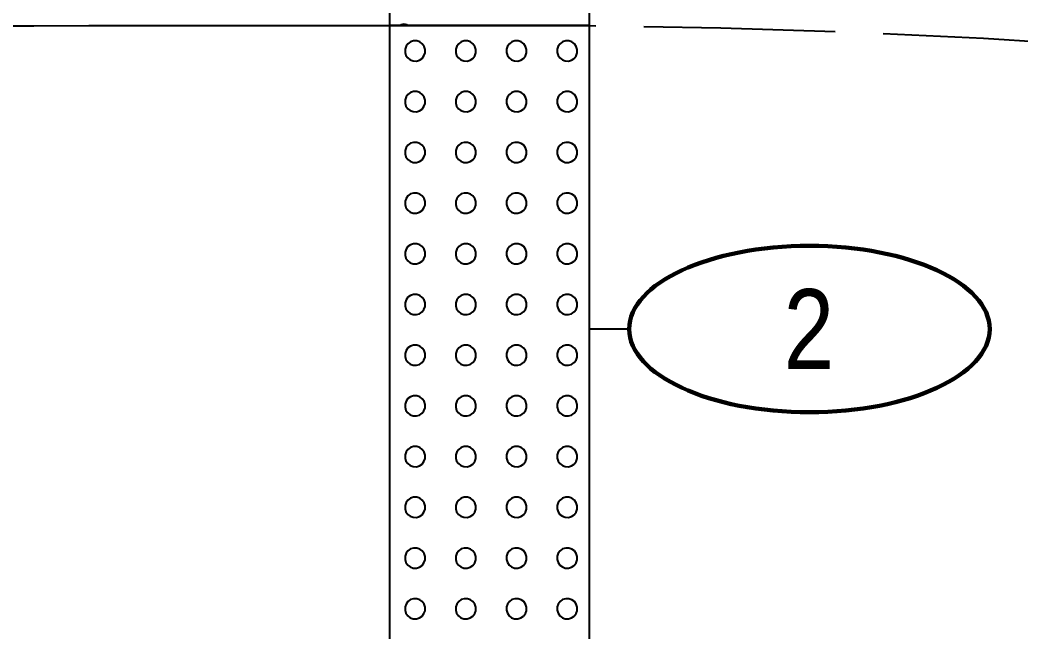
# Model space of a CAD drawing. Extents: x -582 to 653, y -817 to -3.
# Drawn here: x -30.1 to -17.56, y -223.19 to -215.52 of the extents above; entities that cross this region are included whole.
import ezdxf
from ezdxf.enums import TextEntityAlignment as Align

# ---------------------------------------------------------------- set-up
doc = ezdxf.new("R2010")
doc.units = 0
doc.header["$LTSCALE"] = 0.4
doc.linetypes.add('LONG_DASHED', pattern=[7.5, 6, -1.5])
doc.layers.add('26', color=7, linetype='LONG_DASHED', lineweight=40)
doc.layers.add('27', color=7, linetype='Continuous', lineweight=40)

msp = doc.modelspace()

# ---------------------------------------------------------------- linework, layer by layer
at = {"layer": '26'}
msp.add_spline([(-40.288, -215.7398), (-29.2387, -215.5929), (-25.4713, -215.5929), (-22.9713, -215.5929), (3.2787, -218.2344)], degree=3, dxfattribs=at)
at = {"layer": '27'}
for p, q in [((-29.2387, -215.5929), (-25.4713, -215.5929)), ((-22.4714, -219.3929), (-22.9714, -219.3929))]:
    msp.add_line(p, q, dxfattribs=at)
for points in [[(-25.4713, -200.5929), (-22.9713, -200.5929), (-22.9713, -215.5929), (-25.4713, -215.5929)], [(-25.4713, -215.5929), (-22.9713, -215.5929), (-22.9713, -226.0929), (-25.4713, -226.0929)], [(-25.2551, -215.5834), (-25.2932, -215.5732), (-25.3313, -215.5834), (-25.3408, -215.5929), (-25.2455, -215.5929)], [(-25.0267, -215.9104), (-25.0283, -215.8907), (-25.0404, -215.853), (-25.0636, -215.8209), (-25.0954, -215.7975), (-25.133, -215.785), (-25.1725, -215.7847), (-25.2103, -215.7965), (-25.2426, -215.8194), (-25.2662, -215.851), (-25.2791, -215.8885), (-25.2798, -215.928), (-25.2683, -215.9659), (-25.2457, -215.9983), (-25.2142, -216.0223), (-25.1769, -216.0354), (-25.1374, -216.0365), (-25.0994, -216.0253), (-25.0667, -216.003), (-25.0425, -215.9718), (-25.029, -215.9346)], [(-24.3917, -215.9104), (-24.3933, -215.8907), (-24.4054, -215.853), (-24.4286, -215.8209), (-24.4604, -215.7975), (-24.498, -215.785), (-24.5375, -215.7847), (-24.5753, -215.7965), (-24.6076, -215.8194), (-24.6312, -215.851), (-24.6441, -215.8885), (-24.6448, -215.928), (-24.6333, -215.9659), (-24.6107, -215.9983), (-24.5792, -216.0223), (-24.5419, -216.0354), (-24.5024, -216.0365), (-24.4644, -216.0253), (-24.4317, -216.003), (-24.4075, -215.9718), (-24.394, -215.9346)], [(-23.7567, -215.9104), (-23.7583, -215.8907), (-23.7704, -215.853), (-23.7936, -215.8209), (-23.8254, -215.7975), (-23.863, -215.785), (-23.9025, -215.7847), (-23.9403, -215.7965), (-23.9726, -215.8194), (-23.9962, -215.851), (-24.0091, -215.8885), (-24.0098, -215.928), (-23.9983, -215.9659), (-23.9757, -215.9983), (-23.9442, -216.0223), (-23.9069, -216.0354), (-23.8674, -216.0365), (-23.8294, -216.0253), (-23.7967, -216.003), (-23.7725, -215.9718), (-23.759, -215.9346)], [(-23.1217, -215.9104), (-23.1233, -215.8907), (-23.1354, -215.853), (-23.1586, -215.8209), (-23.1904, -215.7975), (-23.228, -215.785), (-23.2675, -215.7847), (-23.3053, -215.7965), (-23.3376, -215.8194), (-23.3612, -215.851), (-23.3741, -215.8885), (-23.3748, -215.928), (-23.3633, -215.9659), (-23.3407, -215.9983), (-23.3092, -216.0223), (-23.2719, -216.0354), (-23.2324, -216.0365), (-23.1944, -216.0253), (-23.1617, -216.003), (-23.1375, -215.9718), (-23.124, -215.9346)], [(-25.0267, -216.5454), (-25.0283, -216.5257), (-25.0404, -216.488), (-25.0636, -216.4559), (-25.0954, -216.4325), (-25.133, -216.42), (-25.1725, -216.4197), (-25.2103, -216.4315), (-25.2426, -216.4544), (-25.2662, -216.486), (-25.2791, -216.5235), (-25.2798, -216.563), (-25.2683, -216.6009), (-25.2457, -216.6333), (-25.2142, -216.6573), (-25.1769, -216.6704), (-25.1374, -216.6715), (-25.0994, -216.6603), (-25.0667, -216.638), (-25.0425, -216.6068), (-25.029, -216.5696)], [(-24.3917, -216.5454), (-24.3933, -216.5257), (-24.4054, -216.488), (-24.4286, -216.4559), (-24.4604, -216.4325), (-24.498, -216.42), (-24.5375, -216.4197), (-24.5753, -216.4315), (-24.6076, -216.4544), (-24.6312, -216.486), (-24.6441, -216.5235), (-24.6448, -216.563), (-24.6333, -216.6009), (-24.6107, -216.6333), (-24.5792, -216.6573), (-24.5419, -216.6704), (-24.5024, -216.6715), (-24.4644, -216.6603), (-24.4317, -216.638), (-24.4075, -216.6068), (-24.394, -216.5696)], [(-23.7567, -216.5454), (-23.7583, -216.5257), (-23.7704, -216.488), (-23.7936, -216.4559), (-23.8254, -216.4325), (-23.863, -216.42), (-23.9025, -216.4197), (-23.9403, -216.4315), (-23.9726, -216.4544), (-23.9962, -216.486), (-24.0091, -216.5235), (-24.0098, -216.563), (-23.9983, -216.6009), (-23.9757, -216.6333), (-23.9442, -216.6573), (-23.9069, -216.6704), (-23.8674, -216.6715), (-23.8294, -216.6603), (-23.7967, -216.638), (-23.7725, -216.6068), (-23.759, -216.5696)], [(-23.1217, -216.5454), (-23.1233, -216.5257), (-23.1354, -216.488), (-23.1586, -216.4559), (-23.1904, -216.4325), (-23.228, -216.42), (-23.2675, -216.4197), (-23.3053, -216.4315), (-23.3376, -216.4544), (-23.3612, -216.486), (-23.3741, -216.5235), (-23.3748, -216.563), (-23.3633, -216.6009), (-23.3407, -216.6333), (-23.3092, -216.6573), (-23.2719, -216.6704), (-23.2324, -216.6715), (-23.1944, -216.6603), (-23.1617, -216.638), (-23.1375, -216.6068), (-23.124, -216.5696)], [(-25.0267, -217.1804), (-25.0283, -217.1607), (-25.0404, -217.123), (-25.0636, -217.0909), (-25.0954, -217.0675), (-25.133, -217.055), (-25.1725, -217.0547), (-25.2103, -217.0665), (-25.2426, -217.0894), (-25.2662, -217.121), (-25.2791, -217.1585), (-25.2798, -217.198), (-25.2683, -217.2359), (-25.2457, -217.2683), (-25.2142, -217.2923), (-25.1769, -217.3054), (-25.1374, -217.3065), (-25.0994, -217.2953), (-25.0667, -217.273), (-25.0425, -217.2418), (-25.029, -217.2046)], [(-24.3917, -217.1804), (-24.3933, -217.1607), (-24.4054, -217.123), (-24.4286, -217.0909), (-24.4604, -217.0675), (-24.498, -217.055), (-24.5375, -217.0547), (-24.5753, -217.0665), (-24.6076, -217.0894), (-24.6312, -217.121), (-24.6441, -217.1585), (-24.6448, -217.198), (-24.6333, -217.2359), (-24.6107, -217.2683), (-24.5792, -217.2923), (-24.5419, -217.3054), (-24.5024, -217.3065), (-24.4644, -217.2953), (-24.4317, -217.273), (-24.4075, -217.2418), (-24.394, -217.2046)], [(-23.7567, -217.1804), (-23.7583, -217.1607), (-23.7704, -217.123), (-23.7936, -217.0909), (-23.8254, -217.0675), (-23.863, -217.055), (-23.9025, -217.0547), (-23.9403, -217.0665), (-23.9726, -217.0894), (-23.9962, -217.121), (-24.0091, -217.1585), (-24.0098, -217.198), (-23.9983, -217.2359), (-23.9757, -217.2683), (-23.9442, -217.2923), (-23.9069, -217.3054), (-23.8674, -217.3065), (-23.8294, -217.2953), (-23.7967, -217.273), (-23.7725, -217.2418), (-23.759, -217.2046)], [(-23.1217, -217.1804), (-23.1233, -217.1607), (-23.1354, -217.123), (-23.1586, -217.0909), (-23.1904, -217.0675), (-23.228, -217.055), (-23.2675, -217.0547), (-23.3053, -217.0665), (-23.3376, -217.0894), (-23.3612, -217.121), (-23.3741, -217.1585), (-23.3748, -217.198), (-23.3633, -217.2359), (-23.3407, -217.2683), (-23.3092, -217.2923), (-23.2719, -217.3054), (-23.2324, -217.3065), (-23.1944, -217.2953), (-23.1617, -217.273), (-23.1375, -217.2418), (-23.124, -217.2046)], [(-25.0267, -217.8154), (-25.0283, -217.7957), (-25.0404, -217.758), (-25.0636, -217.7259), (-25.0954, -217.7025), (-25.133, -217.69), (-25.1725, -217.6897), (-25.2103, -217.7015), (-25.2426, -217.7244), (-25.2662, -217.756), (-25.2791, -217.7935), (-25.2798, -217.833), (-25.2683, -217.8709), (-25.2457, -217.9033), (-25.2142, -217.9273), (-25.1769, -217.9404), (-25.1374, -217.9415), (-25.0994, -217.9303), (-25.0667, -217.908), (-25.0425, -217.8768), (-25.029, -217.8396)], [(-24.3917, -217.8154), (-24.3933, -217.7957), (-24.4054, -217.758), (-24.4286, -217.7259), (-24.4604, -217.7025), (-24.498, -217.69), (-24.5375, -217.6897), (-24.5753, -217.7015), (-24.6076, -217.7244), (-24.6312, -217.756), (-24.6441, -217.7935), (-24.6448, -217.833), (-24.6333, -217.8709), (-24.6107, -217.9033), (-24.5792, -217.9273), (-24.5419, -217.9404), (-24.5024, -217.9415), (-24.4644, -217.9303), (-24.4317, -217.908), (-24.4075, -217.8768), (-24.394, -217.8396)], [(-23.7567, -217.8154), (-23.7583, -217.7957), (-23.7704, -217.758), (-23.7936, -217.7259), (-23.8254, -217.7025), (-23.863, -217.69), (-23.9025, -217.6897), (-23.9403, -217.7015), (-23.9726, -217.7244), (-23.9962, -217.756), (-24.0091, -217.7935), (-24.0098, -217.833), (-23.9983, -217.8709), (-23.9757, -217.9033), (-23.9442, -217.9273), (-23.9069, -217.9404), (-23.8674, -217.9415), (-23.8294, -217.9303), (-23.7967, -217.908), (-23.7725, -217.8768), (-23.759, -217.8396)], [(-23.1217, -217.8154), (-23.1233, -217.7957), (-23.1354, -217.758), (-23.1586, -217.7259), (-23.1904, -217.7025), (-23.228, -217.69), (-23.2675, -217.6897), (-23.3053, -217.7015), (-23.3376, -217.7244), (-23.3612, -217.756), (-23.3741, -217.7935), (-23.3748, -217.833), (-23.3633, -217.8709), (-23.3407, -217.9033), (-23.3092, -217.9273), (-23.2719, -217.9404), (-23.2324, -217.9415), (-23.1944, -217.9303), (-23.1617, -217.908), (-23.1375, -217.8768), (-23.124, -217.8396)], [(-25.0267, -218.4504), (-25.0283, -218.4307), (-25.0404, -218.393), (-25.0636, -218.3609), (-25.0954, -218.3375), (-25.133, -218.325), (-25.1725, -218.3247), (-25.2103, -218.3365), (-25.2426, -218.3594), (-25.2662, -218.391), (-25.2791, -218.4285), (-25.2798, -218.468), (-25.2683, -218.5059), (-25.2457, -218.5383), (-25.2142, -218.5623), (-25.1769, -218.5754), (-25.1374, -218.5765), (-25.0994, -218.5653), (-25.0667, -218.543), (-25.0425, -218.5118), (-25.029, -218.4746)], [(-24.3917, -218.4504), (-24.3933, -218.4307), (-24.4054, -218.393), (-24.4286, -218.3609), (-24.4604, -218.3375), (-24.498, -218.325), (-24.5375, -218.3247), (-24.5753, -218.3365), (-24.6076, -218.3594), (-24.6312, -218.391), (-24.6441, -218.4285), (-24.6448, -218.468), (-24.6333, -218.5059), (-24.6107, -218.5383), (-24.5792, -218.5623), (-24.5419, -218.5754), (-24.5024, -218.5765), (-24.4644, -218.5653), (-24.4317, -218.543), (-24.4075, -218.5118), (-24.394, -218.4746)], [(-23.7567, -218.4504), (-23.7583, -218.4307), (-23.7704, -218.393), (-23.7936, -218.3609), (-23.8254, -218.3375), (-23.863, -218.325), (-23.9025, -218.3247), (-23.9403, -218.3365), (-23.9726, -218.3594), (-23.9962, -218.391), (-24.0091, -218.4285), (-24.0098, -218.468), (-23.9983, -218.5059), (-23.9757, -218.5383), (-23.9442, -218.5623), (-23.9069, -218.5754), (-23.8674, -218.5765), (-23.8294, -218.5653), (-23.7967, -218.543), (-23.7725, -218.5118), (-23.759, -218.4746)], [(-23.1217, -218.4504), (-23.1233, -218.4307), (-23.1354, -218.393), (-23.1586, -218.3609), (-23.1904, -218.3375), (-23.228, -218.325), (-23.2675, -218.3247), (-23.3053, -218.3365), (-23.3376, -218.3594), (-23.3612, -218.391), (-23.3741, -218.4285), (-23.3748, -218.468), (-23.3633, -218.5059), (-23.3407, -218.5383), (-23.3092, -218.5623), (-23.2719, -218.5754), (-23.2324, -218.5765), (-23.1944, -218.5653), (-23.1617, -218.543), (-23.1375, -218.5118), (-23.124, -218.4746)], [(-25.0267, -219.0854), (-25.0283, -219.0657), (-25.0404, -219.028), (-25.0636, -218.9959), (-25.0954, -218.9725), (-25.133, -218.96), (-25.1725, -218.9597), (-25.2103, -218.9715), (-25.2426, -218.9944), (-25.2662, -219.026), (-25.2791, -219.0635), (-25.2798, -219.103), (-25.2683, -219.1409), (-25.2457, -219.1733), (-25.2142, -219.1973), (-25.1769, -219.2104), (-25.1374, -219.2115), (-25.0994, -219.2003), (-25.0667, -219.178), (-25.0425, -219.1468), (-25.029, -219.1096)], [(-24.3917, -219.0854), (-24.3933, -219.0657), (-24.4054, -219.028), (-24.4286, -218.9959), (-24.4604, -218.9725), (-24.498, -218.96), (-24.5375, -218.9597), (-24.5753, -218.9715), (-24.6076, -218.9944), (-24.6312, -219.026), (-24.6441, -219.0635), (-24.6448, -219.103), (-24.6333, -219.1409), (-24.6107, -219.1733), (-24.5792, -219.1973), (-24.5419, -219.2104), (-24.5024, -219.2115), (-24.4644, -219.2003), (-24.4317, -219.178), (-24.4075, -219.1468), (-24.394, -219.1096)], [(-23.7567, -219.0854), (-23.7583, -219.0657), (-23.7704, -219.028), (-23.7936, -218.9959), (-23.8254, -218.9725), (-23.863, -218.96), (-23.9025, -218.9597), (-23.9403, -218.9715), (-23.9726, -218.9944), (-23.9962, -219.026), (-24.0091, -219.0635), (-24.0098, -219.103), (-23.9983, -219.1409), (-23.9757, -219.1733), (-23.9442, -219.1973), (-23.9069, -219.2104), (-23.8674, -219.2115), (-23.8294, -219.2003), (-23.7967, -219.178), (-23.7725, -219.1468), (-23.759, -219.1096)], [(-23.1217, -219.0854), (-23.1233, -219.0657), (-23.1354, -219.028), (-23.1586, -218.9959), (-23.1904, -218.9725), (-23.228, -218.96), (-23.2675, -218.9597), (-23.3053, -218.9715), (-23.3376, -218.9944), (-23.3612, -219.026), (-23.3741, -219.0635), (-23.3748, -219.103), (-23.3633, -219.1409), (-23.3407, -219.1733), (-23.3092, -219.1973), (-23.2719, -219.2104), (-23.2324, -219.2115), (-23.1944, -219.2003), (-23.1617, -219.178), (-23.1375, -219.1468), (-23.124, -219.1096)], [(-25.0267, -219.7204), (-25.0283, -219.7007), (-25.0404, -219.663), (-25.0636, -219.6309), (-25.0954, -219.6075), (-25.133, -219.595), (-25.1725, -219.5947), (-25.2103, -219.6065), (-25.2426, -219.6294), (-25.2662, -219.661), (-25.2791, -219.6985), (-25.2798, -219.738), (-25.2683, -219.7759), (-25.2457, -219.8083), (-25.2142, -219.8323), (-25.1769, -219.8454), (-25.1374, -219.8465), (-25.0994, -219.8353), (-25.0667, -219.813), (-25.0425, -219.7818), (-25.029, -219.7446)], [(-24.3917, -219.7204), (-24.3933, -219.7007), (-24.4054, -219.663), (-24.4286, -219.6309), (-24.4604, -219.6075), (-24.498, -219.595), (-24.5375, -219.5947), (-24.5753, -219.6065), (-24.6076, -219.6294), (-24.6312, -219.661), (-24.6441, -219.6985), (-24.6448, -219.738), (-24.6333, -219.7759), (-24.6107, -219.8083), (-24.5792, -219.8323), (-24.5419, -219.8454), (-24.5024, -219.8465), (-24.4644, -219.8353), (-24.4317, -219.813), (-24.4075, -219.7818), (-24.394, -219.7446)], [(-23.7567, -219.7204), (-23.7583, -219.7007), (-23.7704, -219.663), (-23.7936, -219.6309), (-23.8254, -219.6075), (-23.863, -219.595), (-23.9025, -219.5947), (-23.9403, -219.6065), (-23.9726, -219.6294), (-23.9962, -219.661), (-24.0091, -219.6985), (-24.0098, -219.738), (-23.9983, -219.7759), (-23.9757, -219.8083), (-23.9442, -219.8323), (-23.9069, -219.8454), (-23.8674, -219.8465), (-23.8294, -219.8353), (-23.7967, -219.813), (-23.7725, -219.7818), (-23.759, -219.7446)], [(-23.1217, -219.7204), (-23.1233, -219.7007), (-23.1354, -219.663), (-23.1586, -219.6309), (-23.1904, -219.6075), (-23.228, -219.595), (-23.2675, -219.5947), (-23.3053, -219.6065), (-23.3376, -219.6294), (-23.3612, -219.661), (-23.3741, -219.6985), (-23.3748, -219.738), (-23.3633, -219.7759), (-23.3407, -219.8083), (-23.3092, -219.8323), (-23.2719, -219.8454), (-23.2324, -219.8465), (-23.1944, -219.8353), (-23.1617, -219.813), (-23.1375, -219.7818), (-23.124, -219.7446)], [(-25.0267, -220.3554), (-25.0283, -220.3357), (-25.0404, -220.298), (-25.0636, -220.2659), (-25.0954, -220.2425), (-25.133, -220.23), (-25.1725, -220.2297), (-25.2103, -220.2415), (-25.2426, -220.2644), (-25.2662, -220.296), (-25.2791, -220.3335), (-25.2798, -220.373), (-25.2683, -220.4109), (-25.2457, -220.4433), (-25.2142, -220.4673), (-25.1769, -220.4804), (-25.1374, -220.4815), (-25.0994, -220.4703), (-25.0667, -220.448), (-25.0425, -220.4168), (-25.029, -220.3796)], [(-24.3917, -220.3554), (-24.3933, -220.3357), (-24.4054, -220.298), (-24.4286, -220.2659), (-24.4604, -220.2425), (-24.498, -220.23), (-24.5375, -220.2297), (-24.5753, -220.2415), (-24.6076, -220.2644), (-24.6312, -220.296), (-24.6441, -220.3335), (-24.6448, -220.373), (-24.6333, -220.4109), (-24.6107, -220.4433), (-24.5792, -220.4673), (-24.5419, -220.4804), (-24.5024, -220.4815), (-24.4644, -220.4703), (-24.4317, -220.448), (-24.4075, -220.4168), (-24.394, -220.3796)], [(-23.7567, -220.3554), (-23.7583, -220.3357), (-23.7704, -220.298), (-23.7936, -220.2659), (-23.8254, -220.2425), (-23.863, -220.23), (-23.9025, -220.2297), (-23.9403, -220.2415), (-23.9726, -220.2644), (-23.9962, -220.296), (-24.0091, -220.3335), (-24.0098, -220.373), (-23.9983, -220.4109), (-23.9757, -220.4433), (-23.9442, -220.4673), (-23.9069, -220.4804), (-23.8674, -220.4815), (-23.8294, -220.4703), (-23.7967, -220.448), (-23.7725, -220.4168), (-23.759, -220.3796)], [(-23.1217, -220.3554), (-23.1233, -220.3357), (-23.1354, -220.298), (-23.1586, -220.2659), (-23.1904, -220.2425), (-23.228, -220.23), (-23.2675, -220.2297), (-23.3053, -220.2415), (-23.3376, -220.2644), (-23.3612, -220.296), (-23.3741, -220.3335), (-23.3748, -220.373), (-23.3633, -220.4109), (-23.3407, -220.4433), (-23.3092, -220.4673), (-23.2719, -220.4804), (-23.2324, -220.4815), (-23.1944, -220.4703), (-23.1617, -220.448), (-23.1375, -220.4168), (-23.124, -220.3796)], [(-25.0267, -220.9904), (-25.0283, -220.9707), (-25.0404, -220.933), (-25.0636, -220.9009), (-25.0954, -220.8775), (-25.133, -220.865), (-25.1725, -220.8647), (-25.2103, -220.8765), (-25.2426, -220.8994), (-25.2662, -220.931), (-25.2791, -220.9685), (-25.2798, -221.008), (-25.2683, -221.0459), (-25.2457, -221.0783), (-25.2142, -221.1023), (-25.1769, -221.1154), (-25.1374, -221.1165), (-25.0994, -221.1053), (-25.0667, -221.083), (-25.0425, -221.0518), (-25.029, -221.0146)], [(-24.3917, -220.9904), (-24.3933, -220.9707), (-24.4054, -220.933), (-24.4286, -220.9009), (-24.4604, -220.8775), (-24.498, -220.865), (-24.5375, -220.8647), (-24.5753, -220.8765), (-24.6076, -220.8994), (-24.6312, -220.931), (-24.6441, -220.9685), (-24.6448, -221.008), (-24.6333, -221.0459), (-24.6107, -221.0783), (-24.5792, -221.1023), (-24.5419, -221.1154), (-24.5024, -221.1165), (-24.4644, -221.1053), (-24.4317, -221.083), (-24.4075, -221.0518), (-24.394, -221.0146)], [(-23.7567, -220.9904), (-23.7583, -220.9707), (-23.7704, -220.933), (-23.7936, -220.9009), (-23.8254, -220.8775), (-23.863, -220.865), (-23.9025, -220.8647), (-23.9403, -220.8765), (-23.9726, -220.8994), (-23.9962, -220.931), (-24.0091, -220.9685), (-24.0098, -221.008), (-23.9983, -221.0459), (-23.9757, -221.0783), (-23.9442, -221.1023), (-23.9069, -221.1154), (-23.8674, -221.1165), (-23.8294, -221.1053), (-23.7967, -221.083), (-23.7725, -221.0518), (-23.759, -221.0146)], [(-23.1217, -220.9904), (-23.1233, -220.9707), (-23.1354, -220.933), (-23.1586, -220.9009), (-23.1904, -220.8775), (-23.228, -220.865), (-23.2675, -220.8647), (-23.3053, -220.8765), (-23.3376, -220.8994), (-23.3612, -220.931), (-23.3741, -220.9685), (-23.3748, -221.008), (-23.3633, -221.0459), (-23.3407, -221.0783), (-23.3092, -221.1023), (-23.2719, -221.1154), (-23.2324, -221.1165), (-23.1944, -221.1053), (-23.1617, -221.083), (-23.1375, -221.0518), (-23.124, -221.0146)], [(-25.0267, -221.6254), (-25.0283, -221.6057), (-25.0404, -221.568), (-25.0636, -221.5359), (-25.0954, -221.5125), (-25.133, -221.5), (-25.1725, -221.4997), (-25.2103, -221.5115), (-25.2426, -221.5344), (-25.2662, -221.566), (-25.2791, -221.6035), (-25.2798, -221.643), (-25.2683, -221.6809), (-25.2457, -221.7133), (-25.2142, -221.7373), (-25.1769, -221.7504), (-25.1374, -221.7515), (-25.0994, -221.7403), (-25.0667, -221.718), (-25.0425, -221.6868), (-25.029, -221.6496)], [(-24.3917, -221.6254), (-24.3933, -221.6057), (-24.4054, -221.568), (-24.4286, -221.5359), (-24.4604, -221.5125), (-24.498, -221.5), (-24.5375, -221.4997), (-24.5753, -221.5115), (-24.6076, -221.5344), (-24.6312, -221.566), (-24.6441, -221.6035), (-24.6448, -221.643), (-24.6333, -221.6809), (-24.6107, -221.7133), (-24.5792, -221.7373), (-24.5419, -221.7504), (-24.5024, -221.7515), (-24.4644, -221.7403), (-24.4317, -221.718), (-24.4075, -221.6868), (-24.394, -221.6496)], [(-23.7567, -221.6254), (-23.7583, -221.6057), (-23.7704, -221.568), (-23.7936, -221.5359), (-23.8254, -221.5125), (-23.863, -221.5), (-23.9025, -221.4997), (-23.9403, -221.5115), (-23.9726, -221.5344), (-23.9962, -221.566), (-24.0091, -221.6035), (-24.0098, -221.643), (-23.9983, -221.6809), (-23.9757, -221.7133), (-23.9442, -221.7373), (-23.9069, -221.7504), (-23.8674, -221.7515), (-23.8294, -221.7403), (-23.7967, -221.718), (-23.7725, -221.6868), (-23.759, -221.6496)], [(-23.1217, -221.6254), (-23.1233, -221.6057), (-23.1354, -221.568), (-23.1586, -221.5359), (-23.1904, -221.5125), (-23.228, -221.5), (-23.2675, -221.4997), (-23.3053, -221.5115), (-23.3376, -221.5344), (-23.3612, -221.566), (-23.3741, -221.6035), (-23.3748, -221.643), (-23.3633, -221.6809), (-23.3407, -221.7133), (-23.3092, -221.7373), (-23.2719, -221.7504), (-23.2324, -221.7515), (-23.1944, -221.7403), (-23.1617, -221.718), (-23.1375, -221.6868), (-23.124, -221.6496)], [(-25.0267, -222.2604), (-25.0283, -222.2407), (-25.0404, -222.203), (-25.0636, -222.1709), (-25.0954, -222.1475), (-25.133, -222.135), (-25.1725, -222.1347), (-25.2103, -222.1465), (-25.2426, -222.1694), (-25.2662, -222.201), (-25.2791, -222.2385), (-25.2798, -222.278), (-25.2683, -222.3159), (-25.2457, -222.3483), (-25.2142, -222.3723), (-25.1769, -222.3854), (-25.1374, -222.3865), (-25.0994, -222.3753), (-25.0667, -222.353), (-25.0425, -222.3218), (-25.029, -222.2846)], [(-24.3917, -222.2604), (-24.3933, -222.2407), (-24.4054, -222.203), (-24.4286, -222.1709), (-24.4604, -222.1475), (-24.498, -222.135), (-24.5375, -222.1347), (-24.5753, -222.1465), (-24.6076, -222.1694), (-24.6312, -222.201), (-24.6441, -222.2385), (-24.6448, -222.278), (-24.6333, -222.3159), (-24.6107, -222.3483), (-24.5792, -222.3723), (-24.5419, -222.3854), (-24.5024, -222.3865), (-24.4644, -222.3753), (-24.4317, -222.353), (-24.4075, -222.3218), (-24.394, -222.2846)], [(-23.7567, -222.2604), (-23.7583, -222.2407), (-23.7704, -222.203), (-23.7936, -222.1709), (-23.8254, -222.1475), (-23.863, -222.135), (-23.9025, -222.1347), (-23.9403, -222.1465), (-23.9726, -222.1694), (-23.9962, -222.201), (-24.0091, -222.2385), (-24.0098, -222.278), (-23.9983, -222.3159), (-23.9757, -222.3483), (-23.9442, -222.3723), (-23.9069, -222.3854), (-23.8674, -222.3865), (-23.8294, -222.3753), (-23.7967, -222.353), (-23.7725, -222.3218), (-23.759, -222.2846)], [(-23.1217, -222.2604), (-23.1233, -222.2407), (-23.1354, -222.203), (-23.1586, -222.1709), (-23.1904, -222.1475), (-23.228, -222.135), (-23.2675, -222.1347), (-23.3053, -222.1465), (-23.3376, -222.1694), (-23.3612, -222.201), (-23.3741, -222.2385), (-23.3748, -222.278), (-23.3633, -222.3159), (-23.3407, -222.3483), (-23.3092, -222.3723), (-23.2719, -222.3854), (-23.2324, -222.3865), (-23.1944, -222.3753), (-23.1617, -222.353), (-23.1375, -222.3218), (-23.124, -222.2846)], [(-25.0267, -222.8954), (-25.0283, -222.8757), (-25.0404, -222.838), (-25.0636, -222.8059), (-25.0954, -222.7825), (-25.133, -222.77), (-25.1725, -222.7697), (-25.2103, -222.7815), (-25.2426, -222.8044), (-25.2662, -222.836), (-25.2791, -222.8735), (-25.2798, -222.913), (-25.2683, -222.9509), (-25.2457, -222.9833), (-25.2142, -223.0073), (-25.1769, -223.0204), (-25.1374, -223.0215), (-25.0994, -223.0103), (-25.0667, -222.988), (-25.0425, -222.9568), (-25.029, -222.9196)], [(-24.3917, -222.8954), (-24.3933, -222.8757), (-24.4054, -222.838), (-24.4286, -222.8059), (-24.4604, -222.7825), (-24.498, -222.77), (-24.5375, -222.7697), (-24.5753, -222.7815), (-24.6076, -222.8044), (-24.6312, -222.836), (-24.6441, -222.8735), (-24.6448, -222.913), (-24.6333, -222.9509), (-24.6107, -222.9833), (-24.5792, -223.0073), (-24.5419, -223.0204), (-24.5024, -223.0215), (-24.4644, -223.0103), (-24.4317, -222.988), (-24.4075, -222.9568), (-24.394, -222.9196)], [(-23.7567, -222.8954), (-23.7583, -222.8757), (-23.7704, -222.838), (-23.7936, -222.8059), (-23.8254, -222.7825), (-23.863, -222.77), (-23.9025, -222.7697), (-23.9403, -222.7815), (-23.9726, -222.8044), (-23.9962, -222.836), (-24.0091, -222.8735), (-24.0098, -222.913), (-23.9983, -222.9509), (-23.9757, -222.9833), (-23.9442, -223.0073), (-23.9069, -223.0204), (-23.8674, -223.0215), (-23.8294, -223.0103), (-23.7967, -222.988), (-23.7725, -222.9568), (-23.759, -222.9196)], [(-23.1217, -222.8954), (-23.1233, -222.8757), (-23.1354, -222.838), (-23.1586, -222.8059), (-23.1904, -222.7825), (-23.228, -222.77), (-23.2675, -222.7697), (-23.3053, -222.7815), (-23.3376, -222.8044), (-23.3612, -222.836), (-23.3741, -222.8735), (-23.3748, -222.913), (-23.3633, -222.9509), (-23.3407, -222.9833), (-23.3092, -223.0073), (-23.2719, -223.0204), (-23.2324, -223.0215), (-23.1944, -223.0103), (-23.1617, -222.988), (-23.1375, -222.9568), (-23.124, -222.9196)]]:
    msp.add_lwpolyline(points, close=True, dxfattribs=at)
at = {"layer": '27', "lineweight": 100}
msp.add_ellipse((-20.214, -219.3929), major_axis=(2.2574, 0), ratio=0.461538, dxfattribs=at)

# ---------------------------------------------------------------- texts
at = {"layer": '27', "width": 0.85}
msp.add_text('2', height=1, dxfattribs=at).set_placement((-20.2212, -219.8929), align=Align.CENTER)

doc.saveas('drawing.dxf')
